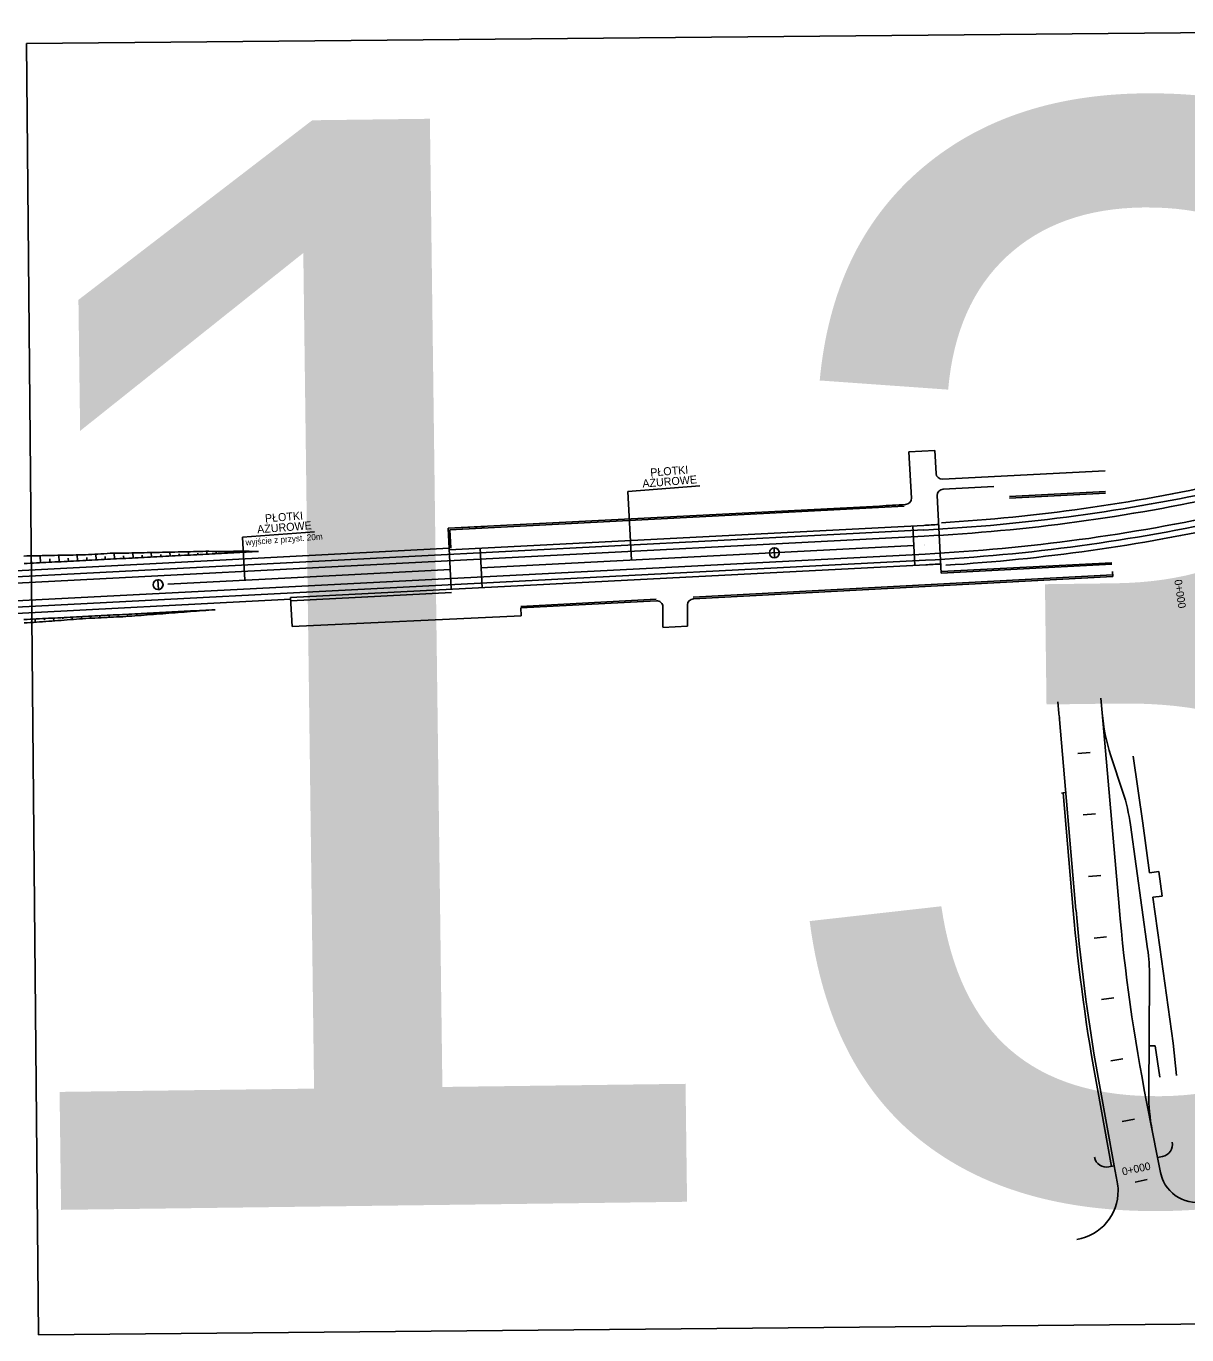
# Model space of a CAD drawing. Extents: x 6503541 to 6503743, y 5888004 to 5888145.
# Drawn here: x 6503672.54 to 6503677.06, y 5888078.09 to 5888083.18 of the extents above; entities that cross this region are included whole.
import ezdxf

# ---------------------------------------------------------------- set-up
doc = ezdxf.new("R2010")
doc.units = 0
doc.layers.add('12', color=7, linetype='Continuous')
doc.layers.add('tabela', color=7, linetype='Continuous')

msp = doc.modelspace()

# ---------------------------------------------------------------- linework, layer by layer
at = {"layer": '12'}
for p, q in [((6503676.0762, 5888081.5266), (6503675.9756, 5888081.5214)), ((6503675.9756, 5888081.5214), (6503675.9848, 5888081.3415)), ((6503676.0762, 5888081.5266), (6503676.0808, 5888081.4374)), ((6503676.7385, 5888081.4473), (6503676.106, 5888081.4147)), ((6503675.1619, 5888081.3889), (6503674.882, 5888081.3673)), ((6503674.882, 5888081.3673), (6503674.8958, 5888081.0995)), ((6503676.0853, 5888081.3507), (6503676.1008, 5888081.0498)), ((6503676.3054, 5888081.3861), (6503676.108, 5888081.3759)), ((6503676.7399, 5888081.3662), (6503676.3665, 5888081.3469)), ((6503676.7402, 5888081.3602), (6503676.3668, 5888081.341)), ((6503674.1834, 5888081.2238), (6503675.8612, 5888081.3103)), ((6503674.1897, 5888081.2181), (6503675.9562, 5888081.3092)), ((6503669.3138, 5888080.8704), (6503676.0337, 5888081.2171)), ((6503669.315, 5888080.8464), (6503676.0349, 5888081.1931)), ((6503673.6635, 5888081.2106), (6503673.3837, 5888081.1889)), ((6503673.3837, 5888081.1889), (6503673.3923, 5888081.0219)), ((6503674.3246, 5888081.2311), (6503674.1834, 5888081.2238)), ((6503674.1956, 5888080.9865), (6503674.1834, 5888081.2238)), ((6503674.1877, 5888081.1399), (6503676.0327, 5888081.2351)), ((6503674.1934, 5888081.1471), (6503674.1897, 5888081.2181)), ((6503675.9903, 5888081.2329), (6503675.9982, 5888081.0795)), ((6503669.3125, 5888080.8943), (6503674.1874, 5888081.1459)), ((6503674.3154, 5888080.9927), (6503674.3076, 5888081.1461)), ((6503674.3115, 5888081.0694), (6503675.9943, 5888081.1562)), ((6503669.3186, 5888080.7769), (6503676.0385, 5888081.1236)), ((6503669.3198, 5888080.7529), (6503676.0397, 5888081.0997)), ((6503672.5615, 5888081.1023), (6503672.5622, 5888081.088)), ((6503672.5982, 5888081.0898), (6503672.5968, 5888081.1173)), ((6503672.6335, 5888081.1049), (6503672.6342, 5888081.0917)), ((6503672.6701, 5888081.0935), (6503672.6688, 5888081.1188)), ((6503672.7054, 5888081.1075), (6503672.7061, 5888081.0954)), ((6503672.742, 5888081.0972), (6503672.7408, 5888081.1203)), ((6503672.7774, 5888081.1101), (6503672.778, 5888081.0991)), ((6503672.8139, 5888081.101), (6503672.8128, 5888081.123)), ((6503672.8493, 5888081.114), (6503672.8499, 5888081.1028)), ((6503672.8858, 5888081.1047), (6503672.8847, 5888081.1268)), ((6503672.9212, 5888081.1167), (6503672.9218, 5888081.1065)), ((6503672.9577, 5888081.1084), (6503672.9567, 5888081.1278)), ((6503672.9932, 5888081.1194), (6503672.9937, 5888081.1102)), ((6503673.0296, 5888081.1121), (6503673.0287, 5888081.1294)), ((6503673.0652, 5888081.1221), (6503673.0656, 5888081.1139)), ((6503673.1015, 5888081.1158), (6503673.1007, 5888081.131)), ((6503673.1371, 5888081.1247), (6503673.1375, 5888081.1177)), ((6503673.1734, 5888081.1195), (6503673.1728, 5888081.1327)), ((6503673.2091, 5888081.1274), (6503673.2094, 5888081.1214)), ((6503673.2453, 5888081.1232), (6503673.2448, 5888081.1342)), ((6503673.2811, 5888081.1293), (6503673.2813, 5888081.1251)), ((6503673.3172, 5888081.1269), (6503673.3169, 5888081.1332)), ((6503673.3531, 5888081.1316), (6503673.3532, 5888081.1288)), ((6503673.3891, 5888081.1306), (6503673.3889, 5888081.1345)), ((6503673.4251, 5888081.1332), (6503673.4251, 5888081.1325)), ((6503673.445, 5888081.1336), (6503673.445, 5888081.1335)), ((6503676.7639, 5888081.0901), (6503676.1005, 5888081.0558)), ((6503676.7642, 5888081.0841), (6503676.1008, 5888081.0498)), ((6503673.5703, 5888080.9542), (6503676.0407, 5888081.0817)), ((6503674.1917, 5888081.0632), (6503673.5729, 5888081.0313)), ((6503676.7679, 5888081.0422), (6503675.1367, 5888080.9557)), ((6503676.7682, 5888081.0362), (6503675.137, 5888080.9497)), ((6503676.7666, 5888081.0554), (6503676.7682, 5888081.0362)), ((6503673.5729, 5888081.0313), (6503673.0935, 5888081.0065)), ((6503669.3211, 5888080.7289), (6503673.5706, 5888080.9482)), ((6503673.5761, 5888080.8419), (6503673.5703, 5888080.9542)), ((6503673.5709, 5888080.9422), (6503674.1962, 5888080.9745)), ((6503674.9927, 5888080.9481), (6503674.4656, 5888080.9201)), ((6503674.993, 5888080.9421), (6503674.4659, 5888080.9141)), ((6503672.7925, 5888080.8821), (6503672.7929, 5888080.874)), ((6503672.8287, 5888080.8799), (6503672.8284, 5888080.884)), ((6503672.8644, 5888080.8858), (6503672.8648, 5888080.8775)), ((6503672.9006, 5888080.8835), (6503672.9004, 5888080.8877)), ((6503672.9363, 5888080.8895), (6503672.9367, 5888080.8814)), ((6503672.9725, 5888080.8876), (6503672.9723, 5888080.8914)), ((6503673.0082, 5888080.8933), (6503673.0085, 5888080.8868)), ((6503673.0443, 5888080.8923), (6503673.0442, 5888080.8951)), ((6503673.0801, 5888080.897), (6503673.0804, 5888080.8923)), ((6503673.1162, 5888080.8969), (6503673.1161, 5888080.8988)), ((6503673.152, 5888080.9007), (6503673.1522, 5888080.8978)), ((6503673.188, 5888080.9016), (6503673.188, 5888080.9025)), ((6503673.2239, 5888080.9044), (6503673.224, 5888080.9033)), ((6503673.2599, 5888080.9061), (6503673.2599, 5888080.9062)), ((6503673.2765, 5888080.907), (6503673.2765, 5888080.9071)), ((6503674.4673, 5888080.8837), (6503673.5761, 5888080.8419)), ((6503674.4659, 5888080.9141), (6503674.4673, 5888080.8837)), ((6503675.0183, 5888080.8387), (6503675.0183, 5888080.9181)), ((6503675.1143, 5888080.8428), (6503675.1143, 5888080.9257)), ((6503672.5768, 5888080.871), (6503672.5774, 5888080.8584)), ((6503672.613, 5888080.8669), (6503672.6127, 5888080.8729)), ((6503672.6487, 5888080.8747), (6503672.6493, 5888080.8637)), ((6503672.6849, 5888080.8715), (6503672.6846, 5888080.8766)), ((6503672.7206, 5888080.8784), (6503672.7211, 5888080.8692)), ((6503672.7568, 5888080.8761), (6503672.7565, 5888080.8803)), ((6503675.0183, 5888080.8385), (6503675.1143, 5888080.8429)), ((6503676.5584, 5888080.5052), (6503676.5549, 5888080.5486)), ((6503676.7268, 5888080.5061), (6503676.7221, 5888080.5628)), ((6503676.5603, 5888080.4885), (6503676.5593, 5888080.4964)), ((6503676.6251, 5888079.7392), (6503676.5611, 5888080.4805)), ((6503676.7925, 5888079.7536), (6503676.7268, 5888080.5061)), ((6503676.7607, 5888080.3396), (6503676.8074, 5888080.1982)), ((6503676.8476, 5888080.3383), (6503676.8846, 5888080.0775)), ((6503676.5681, 5888080.194), (6503676.5749, 5888080.1949)), ((6503676.5856, 5888080.1963), (6503676.5749, 5888080.1949)), ((6503676.6144, 5888079.7382), (6503676.5749, 5888080.1949)), ((6503676.837, 5888080.0709), (6503676.9036, 5888079.5892)), ((6503676.8846, 5888080.0775), (6503676.9113, 5888079.8842)), ((6503676.9113, 5888079.8842), (6503676.947, 5888079.8891)), ((6503676.9601, 5888079.794), (6503676.947, 5888079.8891)), ((6503676.9244, 5888079.7891), (6503676.9601, 5888079.794)), ((6503676.9244, 5888079.7891), (6503676.9512, 5888079.5957)), ((6503676.9512, 5888079.5956), (6503677.0029, 5888079.2215)), ((6503676.9111, 5888079.481), (6503676.908, 5888079.0268)), ((6503676.9092, 5888079.212), (6503676.9332, 5888079.2118)), ((6503676.9518, 5888079.0898), (6503676.9332, 5888079.2118)), ((6503677.0029, 5888079.2215), (6503677.0155, 5888079.0962)), ((6503676.7081, 5888079.0441), (6503676.7636, 5888078.743)), ((6503676.7187, 5888079.0461), (6503676.7742, 5888078.745)), ((6503676.8997, 5888078.9936), (6503676.9215, 5888078.883)), ((6503676.9215, 5888078.883), (6503676.9421, 5888078.778)), ((6503676.7742, 5888078.745), (6503676.7534, 5888078.7408)), ((6503676.7742, 5888078.745), (6503676.7857, 5888078.6828)), ((6503676.9421, 5888078.778), (6503676.9615, 5888078.7817)), ((6503676.9421, 5888078.778), (6503676.9537, 5888078.7193))]:
    msp.add_line(p, q, dxfattribs=at)
for points in [[(6503672.5327, 5888081.116), (6503672.5447, 5888081.1163), (6503672.5567, 5888081.1165), (6503672.5687, 5888081.1168), (6503672.5807, 5888081.117), (6503672.5927, 5888081.1173), (6503672.6047, 5888081.1175), (6503672.6167, 5888081.1178), (6503672.6288, 5888081.118), (6503672.6408, 5888081.1182), (6503672.6528, 5888081.1185), (6503672.6648, 5888081.1187), (6503672.6768, 5888081.119), (6503672.6888, 5888081.1192), (6503672.7008, 5888081.1195), (6503672.7128, 5888081.1197), (6503672.7248, 5888081.1199), (6503672.7368, 5888081.1202), (6503672.7488, 5888081.1204), (6503672.7608, 5888081.1207), (6503672.7728, 5888081.121), (6503672.7848, 5888081.1213), (6503672.7968, 5888081.1218), (6503672.8087, 5888081.1227), (6503672.8207, 5888081.1236), (6503672.8327, 5888081.1243), (6503672.8447, 5888081.1249), (6503672.8567, 5888081.1257), (6503672.8686, 5888081.1264), (6503672.8806, 5888081.127), (6503672.8927, 5888081.1266), (6503672.9047, 5888081.1266), (6503672.9167, 5888081.1268), (6503672.9287, 5888081.1271), (6503672.9407, 5888081.1274), (6503672.9527, 5888081.1277), (6503672.9647, 5888081.1279), (6503672.9767, 5888081.1282), (6503672.9887, 5888081.1285), (6503673.0007, 5888081.1288), (6503673.0127, 5888081.129), (6503673.0247, 5888081.1293), (6503673.0367, 5888081.1296), (6503673.0487, 5888081.1298), (6503673.0607, 5888081.1301), (6503673.0727, 5888081.1304), (6503673.0847, 5888081.1307), (6503673.0967, 5888081.1309), (6503673.1087, 5888081.1312), (6503673.1207, 5888081.1315), (6503673.1327, 5888081.1317), (6503673.1447, 5888081.132), (6503673.1567, 5888081.1323), (6503673.1687, 5888081.1326), (6503673.1807, 5888081.1328), (6503673.1927, 5888081.1331), (6503673.2047, 5888081.1334), (6503673.2167, 5888081.1337), (6503673.2287, 5888081.1339), (6503673.2407, 5888081.1342), (6503673.2527, 5888081.1343), (6503673.2648, 5888081.134), (6503673.2768, 5888081.1337), (6503673.2888, 5888081.1335), (6503673.3009, 5888081.1333), (6503673.3129, 5888081.1332), (6503673.3249, 5888081.1331), (6503673.3369, 5888081.1333), (6503673.3489, 5888081.1342), (6503673.3609, 5888081.1347), (6503673.3729, 5888081.1347), (6503673.3849, 5888081.1345), (6503673.3969, 5888081.1344), (6503673.409, 5888081.1342), (6503673.421, 5888081.134), (6503673.433, 5888081.1338), (6503673.445, 5888081.1335)], [(6503675.451, 5888081.1474), (6503675.453, 5888081.109)], [(6503672.5342, 5888081.0865), (6503672.5462, 5888081.0871), (6503672.5582, 5888081.0878), (6503672.5702, 5888081.0884), (6503672.5822, 5888081.089), (6503672.5942, 5888081.0896), (6503672.6062, 5888081.0902), (6503672.6181, 5888081.0909), (6503672.6301, 5888081.0915), (6503672.6421, 5888081.0921), (6503672.6541, 5888081.0927), (6503672.6661, 5888081.0933), (6503672.6781, 5888081.0939), (6503672.69, 5888081.0946), (6503672.702, 5888081.0952), (6503672.714, 5888081.0958), (6503672.726, 5888081.0964), (6503672.738, 5888081.097), (6503672.75, 5888081.0977), (6503672.7619, 5888081.0983), (6503672.7739, 5888081.0989), (6503672.7859, 5888081.0995), (6503672.7979, 5888081.1001), (6503672.8099, 5888081.1007), (6503672.8219, 5888081.1014), (6503672.8338, 5888081.102), (6503672.8458, 5888081.1026), (6503672.8578, 5888081.1032), (6503672.8698, 5888081.1038), (6503672.8818, 5888081.1045), (6503672.8938, 5888081.1051), (6503672.9058, 5888081.1057), (6503672.9177, 5888081.1063), (6503672.9297, 5888081.1069), (6503672.9417, 5888081.1075), (6503672.9537, 5888081.1082), (6503672.9657, 5888081.1088), (6503672.9777, 5888081.1094), (6503672.9896, 5888081.11), (6503673.0016, 5888081.1106), (6503673.0136, 5888081.1113), (6503673.0256, 5888081.1119), (6503673.0376, 5888081.1125), (6503673.0496, 5888081.1131), (6503673.0615, 5888081.1137), (6503673.0735, 5888081.1144), (6503673.0855, 5888081.115), (6503673.0975, 5888081.1156), (6503673.1095, 5888081.1162), (6503673.1215, 5888081.1168), (6503673.1334, 5888081.1174), (6503673.1454, 5888081.1181), (6503673.1574, 5888081.1187), (6503673.1694, 5888081.1193), (6503673.1814, 5888081.1199), (6503673.1934, 5888081.1205), (6503673.2054, 5888081.1212), (6503673.2173, 5888081.1218), (6503673.2293, 5888081.1224), (6503673.2413, 5888081.123), (6503673.2533, 5888081.1236), (6503673.2653, 5888081.1242), (6503673.2773, 5888081.1249), (6503673.2892, 5888081.1255), (6503673.3012, 5888081.1261), (6503673.3132, 5888081.1267), (6503673.3252, 5888081.1273), (6503673.3372, 5888081.128), (6503673.3492, 5888081.1286), (6503673.3611, 5888081.1292), (6503673.3731, 5888081.1298), (6503673.3851, 5888081.1304), (6503673.3971, 5888081.131), (6503673.4091, 5888081.1317), (6503673.4211, 5888081.1323), (6503673.4331, 5888081.1329), (6503673.445, 5888081.1335)], [(6503673.0542, 5888081.0237), (6503673.0562, 5888080.9854)], [(6503672.5335, 5888080.8688), (6503672.5455, 5888080.8694), (6503672.5574, 5888080.87), (6503672.5694, 5888080.8706), (6503672.5814, 5888080.8712), (6503672.5934, 5888080.8719), (6503672.6054, 5888080.8725), (6503672.6174, 5888080.8731), (6503672.6293, 5888080.8737), (6503672.6413, 5888080.8743), (6503672.6533, 5888080.8749), (6503672.6653, 5888080.8756), (6503672.6773, 5888080.8762), (6503672.6893, 5888080.8768), (6503672.7012, 5888080.8774), (6503672.7132, 5888080.878), (6503672.7252, 5888080.8787), (6503672.7372, 5888080.8793), (6503672.7492, 5888080.8799), (6503672.7612, 5888080.8805), (6503672.7731, 5888080.8811), (6503672.7851, 5888080.8817), (6503672.7971, 5888080.8824), (6503672.8091, 5888080.883), (6503672.8211, 5888080.8836), (6503672.8331, 5888080.8842), (6503672.8451, 5888080.8848), (6503672.857, 5888080.8855), (6503672.869, 5888080.8861), (6503672.881, 5888080.8867), (6503672.893, 5888080.8873), (6503672.905, 5888080.8879), (6503672.917, 5888080.8885), (6503672.9289, 5888080.8892), (6503672.9409, 5888080.8898), (6503672.9529, 5888080.8904), (6503672.9649, 5888080.891), (6503672.9769, 5888080.8916), (6503672.9889, 5888080.8923), (6503673.0008, 5888080.8929), (6503673.0128, 5888080.8935), (6503673.0248, 5888080.8941), (6503673.0368, 5888080.8947), (6503673.0488, 5888080.8954), (6503673.0608, 5888080.896), (6503673.0727, 5888080.8966), (6503673.0847, 5888080.8972), (6503673.0967, 5888080.8978), (6503673.1087, 5888080.8984), (6503673.1207, 5888080.8991), (6503673.1327, 5888080.8997), (6503673.1447, 5888080.9003), (6503673.1566, 5888080.9009), (6503673.1686, 5888080.9015), (6503673.1806, 5888080.9022), (6503673.1926, 5888080.9028), (6503673.2046, 5888080.9034), (6503673.2166, 5888080.904), (6503673.2285, 5888080.9046), (6503673.2405, 5888080.9052), (6503673.2525, 5888080.9059), (6503673.2645, 5888080.9065), (6503673.2705, 5888080.9068)], [(6503672.5341, 5888080.8557), (6503672.5461, 5888080.8565), (6503672.5581, 5888080.8572), (6503672.5701, 5888080.8579), (6503672.5821, 5888080.8587), (6503672.594, 5888080.8595), (6503672.606, 5888080.8604), (6503672.618, 5888080.8614), (6503672.6299, 5888080.8623), (6503672.6419, 5888080.8632), (6503672.6539, 5888080.8641), (6503672.6658, 5888080.865), (6503672.6778, 5888080.8659), (6503672.6898, 5888080.8668), (6503672.7017, 5888080.8677), (6503672.7137, 5888080.8686), (6503672.7257, 5888080.8695), (6503672.7377, 5888080.8705), (6503672.7496, 5888080.8714), (6503672.7616, 5888080.8723), (6503672.7736, 5888080.8731), (6503672.7855, 5888080.8737), (6503672.7975, 5888080.8743), (6503672.8095, 5888080.8748), (6503672.8215, 5888080.8754), (6503672.8335, 5888080.876), (6503672.8455, 5888080.8766), (6503672.8575, 5888080.8771), (6503672.8695, 5888080.8777), (6503672.8814, 5888080.8783), (6503672.8934, 5888080.8789), (6503672.9054, 5888080.8794), (6503672.9174, 5888080.8801), (6503672.9294, 5888080.8809), (6503672.9413, 5888080.8817), (6503672.9533, 5888080.8825), (6503672.9653, 5888080.8833), (6503672.9773, 5888080.8841), (6503672.9892, 5888080.8851), (6503673.0012, 5888080.8863), (6503673.0132, 5888080.8872), (6503673.0251, 5888080.8881), (6503673.0371, 5888080.889), (6503673.0491, 5888080.8899), (6503673.061, 5888080.8909), (6503673.073, 5888080.8918), (6503673.085, 5888080.8927), (6503673.0969, 5888080.8936), (6503673.1089, 5888080.8945), (6503673.1209, 5888080.8954), (6503673.1328, 5888080.8963), (6503673.1448, 5888080.8973), (6503673.1568, 5888080.8982), (6503673.1687, 5888080.8991), (6503673.1807, 5888080.9), (6503673.1927, 5888080.9009), (6503673.2047, 5888080.9018), (6503673.2166, 5888080.9028), (6503673.2286, 5888080.9036), (6503673.2406, 5888080.9045), (6503673.2525, 5888080.9054), (6503673.2645, 5888080.9063), (6503673.2765, 5888080.907)], [(6503676.6805, 5888080.3524), (6503676.6326, 5888080.3483)], [(6503676.7012, 5888080.1133), (6503676.6533, 5888080.1092)], [(6503676.7218, 5888079.8742), (6503676.674, 5888079.8701)], [(6503676.7434, 5888079.6356), (6503676.6956, 5888079.6307)], [(6503676.7717, 5888079.3981), (6503676.7241, 5888079.3916)], [(6503676.8079, 5888079.1616), (6503676.7606, 5888079.1536)], [(6503676.852, 5888078.9265), (6503676.805, 5888078.9169)], [(6503676.8551, 5888078.682), (6503676.9021, 5888078.6921)]]:
    msp.add_lwpolyline(points, dxfattribs=at)
for centre in [(6503675.452, 5888081.1282), (6503673.0552, 5888081.0045)]:
    msp.add_circle(centre, 0.0192, dxfattribs=at)
for centre, radius, start, end in [((6503676.1048, 5888081.4386), 0.024, 182.9539, 272.9539), ((6503675.6645, 5888088.3538), 7.1223, 273.51736, 282.48188), ((6503675.9609, 5888081.3403), 0.024, 273.7799, 2.9539), ((6503675.6657, 5888088.3488), 7.1412, 272.95394, 282.48188), ((6503675.6657, 5888088.3488), 7.1652, 272.95394, 282.48188), ((6503676.1093, 5888081.3519), 0.024, 92.9539, 182.9539), ((6503675.4984, 5888088.3402), 7.0392, 272.95394, 273.77991), ((6503675.6657, 5888088.3488), 7.1232, 272.95394, 273.42407), ((6503675.6657, 5888088.3488), 7.2348, 272.95394, 282.48188), ((6503675.6657, 5888088.3488), 7.2588, 272.95394, 282.48188), ((6503675.6657, 5888088.3488), 7.2828, 273.57139, 282.48188), ((6503675.452, 5888081.1282), 0.0192, 328.5067, 92.9539), ((6503675.452, 5888081.1282), 0.0192, 272.9539, 328.5067), ((6503675.6657, 5888088.3488), 7.2768, 272.95394, 273.41415), ((6503673.0552, 5888081.0045), 0.0192, 328.5067, 92.9539), ((6503673.0552, 5888081.0045), 0.0192, 272.9539, 328.5067), ((6503674.9943, 5888080.9181), 0.024, 360, 93.0359), ((6503675.1383, 5888080.9257), 0.024, 93.0359, 180), ((6503676.7976, 5888080.525), 0.24, 184.7165, 186.8455), ((6503676.322, 5888080.4599), 0.24, 4.9352, 6.8455), ((6503677.4444, 5888080.5655), 0.72, 184.73, 198.2829), ((6503676.1238, 5888079.9723), 0.72, 7.8736, 18.2829), ((6503683.8821, 5888080.3664), 7.2948, 184.93965, 190.44288), ((6503683.8821, 5888080.3664), 7.284, 184.93965, 190.44288), ((6503683.8821, 5888080.3664), 7.116, 184.93965, 191.12264), ((6503676.1911, 5888079.4859), 0.72, 359.6097, 8.2443), ((6503677.6279, 5888079.0219), 0.72, 179.6097, 191.1226), ((6503676.9525, 5888078.8288), 0.048, 280.8044, 10.8044), ((6503676.744, 5888078.7879), 0.048, 191.2311, 281.2311), ((6503677.095, 5888078.7471), 0.144, 191.1226, 205.6784), ((6503676.5969, 5888078.648), 0.192, 279.52, 0.6046), ((6503676.5969, 5888078.648), 0.192, 0.6046, 10.4429), ((6503677.095, 5888078.7471), 0.144, 205.6784, 297.6141)]:
    msp.add_arc(centre, radius, start, end, dxfattribs=at)
at = {"layer": 'tabela'}
for p, q in [((6503672.5429, 5888083.1083), (6503679.7783, 5888083.1758)), ((6503672.5429, 5888083.1083), (6503679.7783, 5888083.1758)), ((6503672.5898, 5888078.0882), (6503672.5429, 5888083.1083)), ((6503672.5898, 5888078.0882), (6503672.5429, 5888083.1083)), ((6503679.8252, 5888078.1557), (6503672.5898, 5888078.0882)), ((6503679.8252, 5888078.1557), (6503672.5898, 5888078.0882))]:
    msp.add_line(p, q, dxfattribs=at)

# ---------------------------------------------------------------- texts
at = {"layer": '12'}
for s, height, rotation, p in [('13', 4.22297, 0.7393, (6503672.2478, 5888078.5685)), ('PŁOTKI', 0.0311, 4.499, (6503674.9705, 5888081.4249)), ('AŻUROWE', 0.0311, 4.499, (6503674.94, 5888081.3821)), ('PŁOTKI', 0.0311, 4.499, (6503673.4722, 5888081.2466)), ('AŻUROWE', 0.0311, 4.499, (6503673.4417, 5888081.2038)), ('wyjście z przyst. 20m', 0.023802, 4.499, (6503673.3963, 5888081.1569)), ('C', 0.0024, 2.9539, (6503676.0355, 5888081.1571)), ('0+000', 0.03, 278.5588, (6503677.007, 5888081.0222)), ('0+000', 0.03, 12.1356, (6503676.8074, 5888078.7073))]:
    msp.add_text(s, height=height, rotation=rotation, dxfattribs=at).set_placement(p)

doc.saveas('drawing.dxf')
